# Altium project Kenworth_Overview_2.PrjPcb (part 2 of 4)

## Sheet T-Type_System.SchDoc: <Document>
size Letter; Engineer: <Engineer>; Organization: UPEL; Address1: USU Power Electronics Lab; Address2: USTAR Building 620, RM 118; Address3: 1600 N 620 E; Address4: North Logan, UT 84341; DocumentNumber: 8; Revision: v1; SheetNumber: 8; SheetTotal: 16
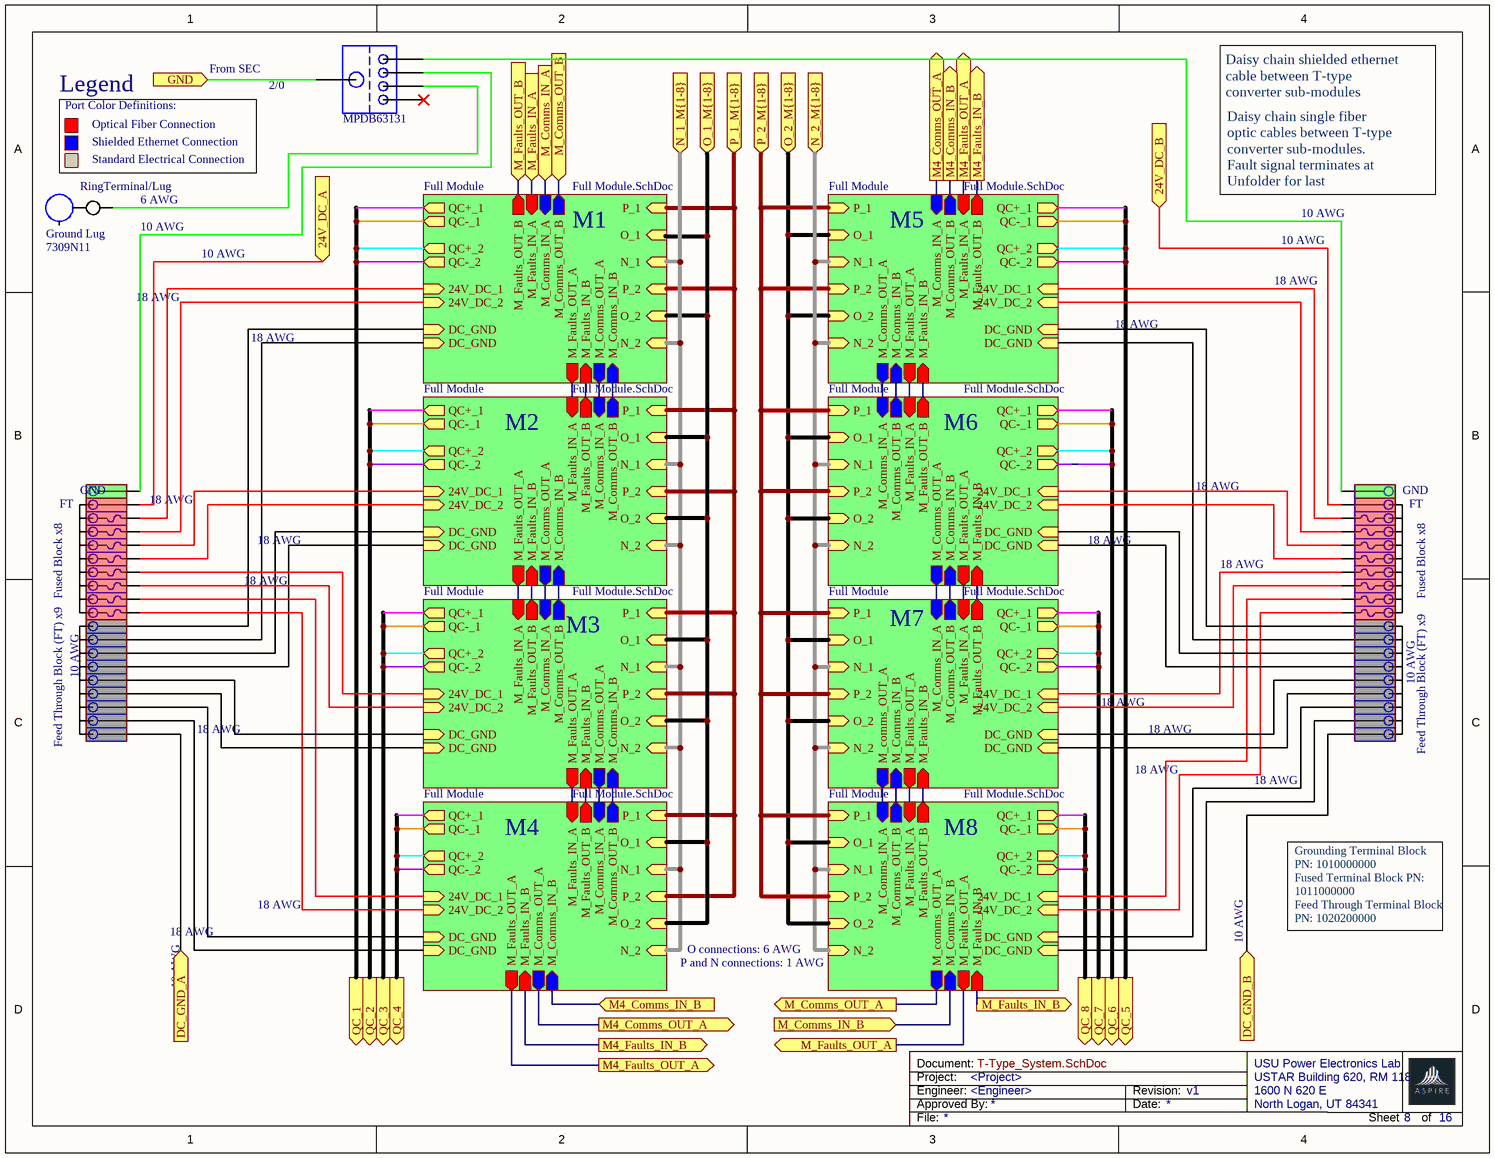
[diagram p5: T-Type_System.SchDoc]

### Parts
(Parts that share a designator on the sheet are numbered #1, #2 ... from top to bottom, then left to right.)
7309N11#1  Ground Lug
*#1  RingTerminal/Lug
J?#1  MPDB63131
J?#2  8_pos_terminal  (value not drawn)
J?#3  8_pos_terminal  (value not drawn)

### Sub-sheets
Full Module = Full Module.SchDoc (file not in this document): M_Faults_IN_B (in), M_Comms_OUT_A (out), M_Faults_IN_A (in), M_Comms_IN_A (in), P_1 (in), O_1 (in), N_1 (in), QC+_1 (out), QC-_1 (out), P_2 (in), O_2 (in), N_2 (in), QC+_2 (out), QC-_2 (out), DC_GND (in), 24V_DC_2 (in), 24V_DC_1 (in), DC_GND (in), M_Comms_OUT_B (out), M_Comms_IN_B (in), M_Faults_OUT_A (out), M_Faults_OUT_B (out)
Full Module = Full Module.SchDoc (file not in this document): M_Faults_IN_B (in), M_Comms_OUT_A (out), M_Faults_OUT_B (out), M_Comms_IN_A (in), P_1 (in), O_1 (in), N_1 (in), QC+_1 (out), QC-_1 (out), P_2 (in), O_2 (in), N_2 (in), QC+_2 (out), QC-_2 (out), DC_GND (in), DC_GND (in), 24V_DC_1 (in), 24V_DC_2 (in), M_Comms_OUT_B (out), M_Comms_IN_B (in), M_Faults_IN_A (in), M_Faults_OUT_A (out)
Full Module = Full Module.SchDoc (file not in this document): M_Faults_IN_B (in), M_comms_OUT_A (out), M_Faults_OUT_B (out), M_Comms_IN_A (in), P_1 (in), O_1 (in), N_1 (in), QC+_1 (out), QC-_1 (out), P_2 (in), O_2 (in), N_2 (in), QC+_2 (out), QC-_2 (out), DC_GND (in), DC_GND (in), 24V_DC_2 (in), 24V_DC_1 (in), M_Comms_OUT_B (out), M_Comms_IN_B (in), M_Faults_OUT_A (out), M_Faults_IN_A (in)
Full Module = Full Module.SchDoc (file not in this document): M_Faults_OUT_A (out), M_comms_OUT_A (out), M_Faults_OUT_B (out), M_Comms_IN_A (in), P_1 (in), O_1 (in), N_1 (in), QC+_1 (out), QC-_1 (out), P_2 (in), O_2 (in), N_2 (in), QC+_2 (out), QC-_2 (out), DC_GND (in), DC_GND (in), 24V_DC_2 (in), 24V_DC_1 (in), M_Comms_OUT_B (out), M_Comms_IN_B (in), M_Faults_IN_A (in), M_Faults_IN_B (in)
Full Module = Full Module.SchDoc (file not in this document): M_Faults_OUT_A (out), M_Comms_OUT_A (out), M_Faults_IN_A (in), M_Comms_IN_A (in), P_1 (in), O_1 (in), N_1 (in), QC+_1 (out), QC-_1 (out), P_2 (in), O_2 (in), N_2 (in), QC+_2 (out), QC-_2 (out), DC_GND (in), 24V_DC_2 (in), 24V_DC_1 (in), DC_GND (in), M_Comms_OUT_B (out), M_Comms_IN_B (in), M_Faults_OUT_B (out), M_Faults_IN_B (in)
Full Module = Full Module.SchDoc (file not in this document): M_Faults_OUT_A (out), M_Comms_OUT_A (out), M_Faults_IN_A (in), M_Comms_IN_A (in), P_1 (in), O_1 (in), N_1 (in), QC+_1 (out), QC-_1 (out), P_2 (in), O_2 (in), N_2 (in), QC+_2 (out), QC-_2 (out), DC_GND (in), DC_GND (in), 24V_DC_1 (in), 24V_DC_2 (in), M_Comms_OUT_B (out), M_Comms_IN_B (in), M_Faults_OUT_B (out), M_Faults_IN_B (in)
Full Module = Full Module.SchDoc (file not in this document): M_Faults_OUT_A (out), M_Comms_OUT_A (out), M_Faults_IN_A (in), M_Comms_IN_A (in), P_1 (in), O_1 (in), N_1 (in), QC+_1 (out), QC-_1 (out), P_2 (in), O_2 (in), N_2 (in), QC+_2 (out), QC-_2 (out), DC_GND (in), DC_GND (in), 24V_DC_2 (in), 24V_DC_1 (in), M_Comms_OUT_B (out), M_Comms_IN_B (in), M_Faults_OUT_B (out), M_Faults_IN_B (in)
Full Module = Full Module.SchDoc (file not in this document): M_Faults_OUT_A (out), M_Comms_OUT_A (out), M_Faults_IN_A (in), M_Comms_IN_A (in), P_1 (in), O_1 (in), N_1 (in), QC+_1 (out), QC-_1 (out), P_2 (in), O_2 (in), N_2 (in), QC+_2 (out), QC-_2 (out), DC_GND (in), DC_GND (in), 24V_DC_2 (in), 24V_DC_1 (in), M_Comms_OUT_B (out), M_Comms_IN_B (in), M_Faults_IN_B (in), M_Faults_OUT_B (out)

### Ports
24V_DC_A (in), 24V_DC_B (in), DC_GND_A (in), DC_GND_B (in), GND (in), M4_Comms_IN_B (in), M4_Comms_IN_B (out), M4_Comms_OUT_A (out), M4_Faults_IN_B (out), M4_Faults_OUT_A (out), M_Comms_IN_A (in), M_Comms_IN_B (in), M_Comms_OUT_A (out), M_Comms_OUT_B (in), M_Faults_IN_A (in), M_Faults_IN_B (out), M_Faults_OUT_A (out), M_Faults_OUT_B (in), N_1_M{1-8} (in), N_2_M{1-8} (in), O_1_M{1-8} (in), O_2_M{1-8} (in), P_1_M{1-8} (in), P_2_M{1-8} (in), QC_1 (out), QC_2 (out), QC_3 (out), QC_4 (out), QC_5 (out), QC_6 (out), QC_7 (out), QC_8 (out)

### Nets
24V_DC_A: J?#2.3 ; port 24V_DC_A
24V_DC_B: J?#3.3 ; port 24V_DC_B
DC_GND_A: J?#2.1 ; port DC_GND_A
DC_GND_B: J?#3.1 ; port DC_GND_B
GND: J?#1.0 ; port GND
M4_Comms_IN_B: port M4_Comms_IN_B, sheet Full Module/M_Comms_OUT_B, sheet Full Module/M_Comms_IN_B
M4_Comms_OUT_A: port M4_Comms_OUT_A, sheet Full Module/M_Comms_IN_A, sheet Full Module/M_Comms_OUT_A
M4_Faults_IN_B: port M4_Faults_IN_B, sheet Full Module/M_Faults_OUT_B, sheet Full Module/M_Faults_IN_B
M4_Faults_OUT_A: port M4_Faults_OUT_A, sheet Full Module/M_Faults_IN_A, sheet Full Module/M_Faults_OUT_A
M_Comms_IN_A: port M_Comms_IN_A, sheet Full Module/M_Comms_IN_A
M_Comms_IN_B: port M_Comms_IN_B, sheet Full Module/M_Comms_IN_B
M_Comms_OUT_A: port M_Comms_OUT_A, sheet Full Module/M_comms_OUT_A
M_Comms_OUT_B: port M_Comms_OUT_B, sheet Full Module/M_Comms_OUT_B
M_Faults_IN_A: port M_Faults_IN_A, sheet Full Module/M_Faults_IN_A
M_Faults_IN_B: port M_Faults_IN_B, sheet Full Module/M_Faults_IN_B
M_Faults_OUT_A: port M_Faults_OUT_A, sheet Full Module/M_Faults_OUT_A
M_Faults_OUT_B: port M_Faults_OUT_B, sheet Full Module/M_Faults_OUT_B
N_1_M{1-8}: port N_1_M{1-8}, sheet Full Module/N_1, sheet Full Module/N_2, sheet Full Module/N_1, sheet Full Module/N_2, sheet Full Module/N_1, sheet Full Module/N_2, sheet Full Module/N_1, sheet Full Module/N_2
N_2_M{1-8}: port N_2_M{1-8}, sheet Full Module/N_1, sheet Full Module/N_2, sheet Full Module/N_1, sheet Full Module/N_2, sheet Full Module/N_1, sheet Full Module/N_2, sheet Full Module/N_1, sheet Full Module/N_2
O_1_M{1-8}: port O_1_M{1-8}, sheet Full Module/O_2, sheet Full Module/O_1, sheet Full Module/O_2, sheet Full Module/O_1, sheet Full Module/O_2, sheet Full Module/O_1, sheet Full Module/O_2
O_2_M{1-8}: port O_2_M{1-8}, sheet Full Module/O_1, sheet Full Module/O_2, sheet Full Module/O_1, sheet Full Module/O_2, sheet Full Module/O_1, sheet Full Module/O_2, sheet Full Module/O_1, sheet Full Module/O_2
P_1_M{1-8}: port P_1_M{1-8}, sheet Full Module/P_1, sheet Full Module/P_2, sheet Full Module/P_1, sheet Full Module/P_2, sheet Full Module/P_1, sheet Full Module/P_2, sheet Full Module/P_1, sheet Full Module/P_2
P_2_M{1-8}: port P_2_M{1-8}, sheet Full Module/P_1, sheet Full Module/P_2, sheet Full Module/P_1, sheet Full Module/P_2, sheet Full Module/P_1, sheet Full Module/P_2, sheet Full Module/P_1, sheet Full Module/P_2
QC_1: port QC_1, sheet Full Module/QC+_1, sheet Full Module/QC-_1, sheet Full Module/QC+_2, sheet Full Module/QC-_2
QC_2: port QC_2, sheet Full Module/QC+_1, sheet Full Module/QC-_1, sheet Full Module/QC+_2, sheet Full Module/QC-_2
QC_3: port QC_3, sheet Full Module/QC+_1, sheet Full Module/QC-_1, sheet Full Module/QC+_2, sheet Full Module/QC-_2
QC_4: port QC_4, sheet Full Module/QC+_1, sheet Full Module/QC-_1, sheet Full Module/QC+_2, sheet Full Module/QC-_2
QC_5: port QC_5, sheet Full Module/QC+_1, sheet Full Module/QC-_1, sheet Full Module/QC+_2, sheet Full Module/QC-_2
QC_6: port QC_6, sheet Full Module/QC+_1, sheet Full Module/QC-_1, sheet Full Module/QC+_2, sheet Full Module/QC-_2
QC_7: port QC_7, sheet Full Module/QC+_1, sheet Full Module/QC-_1, sheet Full Module/QC+_2, sheet Full Module/QC-_2
QC_8: port QC_8, sheet Full Module/QC+_1, sheet Full Module/QC-_1, sheet Full Module/QC+_2, sheet Full Module/QC-_2
Net7309N11#1_5: 7309N11#1.5 *#1.2_13
Net*#1_2_12: *#1.2_12 J?#1.2
NetJ?#1_4: J?#1.4 J?#2.1
NetJ?#1_5: J?#1.5 J?#3.1
NetJ?#2_1: J?#2.1 ; sheet Full Module/DC_GND
NetJ?#2_1: J?#2.1 ; sheet Full Module/DC_GND  [a separate net that carries the same name]
NetJ?#2_1: J?#2.1 ; sheet Full Module/DC_GND  [a separate net that carries the same name]
NetJ?#2_1: J?#2.1 ; sheet Full Module/DC_GND  [a separate net that carries the same name]
NetJ?#2_1: J?#2.1 ; sheet Full Module/DC_GND  [a separate net that carries the same name]
NetJ?#2_1: J?#2.1 ; sheet Full Module/DC_GND  [a separate net that carries the same name]
NetJ?#2_1: J?#2.1 ; sheet Full Module/DC_GND  [a separate net that carries the same name]
NetJ?#2_1: J?#2.1 ; sheet Full Module/DC_GND  [a separate net that carries the same name]
NetJ?#2_3: J?#2.3 ; sheet Full Module/24V_DC_1
NetJ?#2_3: J?#2.3 ; sheet Full Module/24V_DC_2  [a separate net that carries the same name]
NetJ?#2_3: J?#2.3 ; sheet Full Module/24V_DC_2  [a separate net that carries the same name]
NetJ?#2_3: J?#2.3 ; sheet Full Module/24V_DC_1  [a separate net that carries the same name]
NetJ?#2_3: J?#2.3 ; sheet Full Module/24V_DC_2  [a separate net that carries the same name]
NetJ?#2_3: J?#2.3 ; sheet Full Module/24V_DC_1  [a separate net that carries the same name]
NetJ?#2_3: J?#2.3 ; sheet Full Module/24V_DC_2  [a separate net that carries the same name]
NetJ?#2_3: J?#2.3 ; sheet Full Module/24V_DC_1  [a separate net that carries the same name]
NetJ?#3_1: J?#3.1 ; sheet Full Module/DC_GND
NetJ?#3_1: J?#3.1 ; sheet Full Module/DC_GND  [a separate net that carries the same name]
NetJ?#3_1: J?#3.1 ; sheet Full Module/DC_GND  [a separate net that carries the same name]
NetJ?#3_1: J?#3.1 ; sheet Full Module/DC_GND  [a separate net that carries the same name]
NetJ?#3_1: J?#3.1 ; sheet Full Module/DC_GND  [a separate net that carries the same name]
NetJ?#3_1: J?#3.1 ; sheet Full Module/DC_GND  [a separate net that carries the same name]
NetJ?#3_1: J?#3.1 ; sheet Full Module/DC_GND  [a separate net that carries the same name]
NetJ?#3_1: J?#3.1 ; sheet Full Module/DC_GND  [a separate net that carries the same name]
NetJ?#3_3: J?#3.3 ; sheet Full Module/24V_DC_1
NetJ?#3_3: J?#3.3 ; sheet Full Module/24V_DC_2  [a separate net that carries the same name]
NetJ?#3_3: J?#3.3 ; sheet Full Module/24V_DC_2  [a separate net that carries the same name]
NetJ?#3_3: J?#3.3 ; sheet Full Module/24V_DC_1  [a separate net that carries the same name]
NetJ?#3_3: J?#3.3 ; sheet Full Module/24V_DC_2  [a separate net that carries the same name]
NetJ?#3_3: J?#3.3 ; sheet Full Module/24V_DC_1  [a separate net that carries the same name]
NetJ?#3_3: J?#3.3 ; sheet Full Module/24V_DC_2  [a separate net that carries the same name]
NetJ?#3_3: J?#3.3 ; sheet Full Module/24V_DC_1  [a separate net that carries the same name]
(unnamed): sheet Full Module/M_Faults_IN_B, sheet Full Module/M_Faults_OUT_B
(unnamed): sheet Full Module/M_Comms_OUT_A, sheet Full Module/M_Comms_IN_A  [a separate net that carries the same name]
(unnamed): sheet Full Module/M_Comms_IN_B, sheet Full Module/M_Comms_OUT_B  [a separate net that carries the same name]
(unnamed): sheet Full Module/M_Faults_OUT_A, sheet Full Module/M_Faults_IN_A  [a separate net that carries the same name]
(unnamed): sheet Full Module/M_Faults_IN_B, sheet Full Module/M_Faults_OUT_B  [a separate net that carries the same name]
(unnamed): sheet Full Module/M_Comms_OUT_A, sheet Full Module/M_Comms_IN_A  [a separate net that carries the same name]
(unnamed): sheet Full Module/M_Comms_IN_B, sheet Full Module/M_Comms_OUT_B  [a separate net that carries the same name]
(unnamed): sheet Full Module/M_Faults_OUT_A, sheet Full Module/M_Faults_IN_A  [a separate net that carries the same name]
(unnamed): sheet Full Module/M_Faults_IN_B, sheet Full Module/M_Faults_OUT_B  [a separate net that carries the same name]
(unnamed): sheet Full Module/M_comms_OUT_A, sheet Full Module/M_Comms_IN_A  [a separate net that carries the same name]
(unnamed): sheet Full Module/M_Comms_IN_B, sheet Full Module/M_Comms_OUT_B  [a separate net that carries the same name]
(unnamed): sheet Full Module/M_Faults_OUT_A, sheet Full Module/M_Faults_IN_A  [a separate net that carries the same name]
(unnamed): sheet Full Module/M_Faults_OUT_A, sheet Full Module/M_Faults_IN_A  [a separate net that carries the same name]
(unnamed): sheet Full Module/M_Comms_OUT_A, sheet Full Module/M_Comms_IN_A  [a separate net that carries the same name]
(unnamed): sheet Full Module/M_Comms_IN_B, sheet Full Module/M_Comms_OUT_B  [a separate net that carries the same name]
(unnamed): sheet Full Module/M_Faults_IN_B, sheet Full Module/M_Faults_OUT_B  [a separate net that carries the same name]
(unnamed): sheet Full Module/M_Faults_OUT_A, sheet Full Module/M_Faults_IN_A  [a separate net that carries the same name]
(unnamed): sheet Full Module/M_Comms_OUT_A, sheet Full Module/M_Comms_IN_A  [a separate net that carries the same name]
(unnamed): sheet Full Module/M_Comms_IN_B, sheet Full Module/M_Comms_OUT_B  [a separate net that carries the same name]
(unnamed): sheet Full Module/M_Faults_IN_B, sheet Full Module/M_Faults_OUT_B  [a separate net that carries the same name]
(unnamed): sheet Full Module/M_Faults_OUT_A, sheet Full Module/M_Faults_IN_A  [a separate net that carries the same name]
(unnamed): sheet Full Module/M_Comms_OUT_A, sheet Full Module/M_Comms_IN_A  [a separate net that carries the same name]
(unnamed): sheet Full Module/M_Comms_IN_B, sheet Full Module/M_Comms_OUT_B  [a separate net that carries the same name]
(unnamed): sheet Full Module/M_Faults_IN_B, sheet Full Module/M_Faults_OUT_B  [a separate net that carries the same name]

Not connected (* = marked no-connect by the designer): J?#1 1*

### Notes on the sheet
- Legend
- From SEC
- 2/0
- Port Color Definitions:
- Optical Fiber Connection
- Shielded Ethernet Connection
- Standard Electrical Connection
- Daisy chain shielded ethernet
  cable between T-type
  converter sub-modules
- 10 AWG
- 6 AWG
- M1
- M5
- Daisy chain single fiber
  optic cables between T-type
  converter sub-modules.
  Fault signal terminates at
  Unfolder for last
- 18 AWG
- M2
- M6
- (near J?#2) FT
- (near J?#2) GND
- (near J?#3) GND
- (near J?#3) FT
- (near J?#2) Fused Block x8
- (near J?#2) 10 AWG
- M3
- M7
- (near J?#3) 10 AWG
- (near J?#3) Fused Block x8
- (near J?#2) Feed Through Block (FT) x9
- (near J?#3) Feed Through Block (FT) x9
- M4
- M8
- Grounding Terminal Block PN: 1010000000
- Fused Terminal Block PN: 1011000000
- P and N connections: 1 AWG
- O connections: 6 AWG
- Feed Through Terminal Block PN: 1020200000

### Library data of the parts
7309N11#1 = 7309N11
J?#1 = 4_to_1
J?#2 J?#3 = Full_Terminal_Block

## Sheet Coolant_System.SchDoc: <Document>
size Letter; Engineer: <Engineer>; Organization: UPEL; Address1: USU Power Electronics Lab; Address2: USTAR Building 620, RM 118; Address3: 1600 N 620 E; Address4: North Logan, UT 84341; DocumentNumber: 15; Revision: v1; SheetNumber: 15; SheetTotal: 16
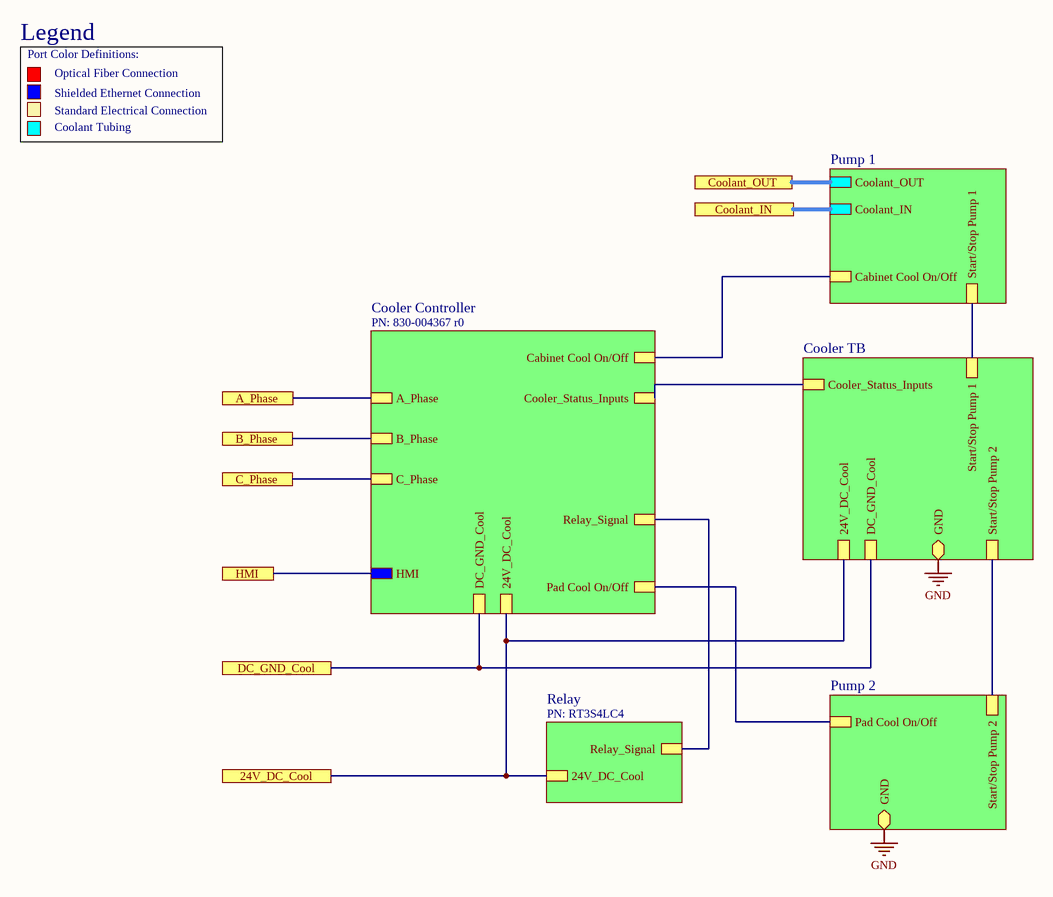
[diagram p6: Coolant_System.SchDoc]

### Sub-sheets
Designator = Cooler Controller (file not in this document): DC_GND_Cool, 24V_DC_Cool, HMI, A_Phase, B_Phase, C_Phase, Relay_Signal, Cooler_Status_Inputs, Pad Cool On/Off, Cabinet Cool On/Off
Designator = Pump 1 (file not in this document): Cabinet Cool On/Off, Coolant_OUT, Coolant_IN, Start/Stop Pump 1
Designator = Pump 2 (file not in this document): Pad Cool On/Off, Start/Stop Pump 2, GND (bidir)
Designator = Cooler TB (file not in this document): Cooler_Status_Inputs, 24V_DC_Cool, DC_GND_Cool, GND (bidir), Start/Stop Pump 1, Start/Stop Pump 2
Relay = Relay (file not in this document): 24V_DC_Cool, Relay_Signal

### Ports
24V_DC_Cool, A_Phase, B_Phase, C_Phase, Coolant_IN, Coolant_OUT, DC_GND_Cool, HMI

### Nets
GND: sheet Designator/GND, sheet Designator/GND
24V_DC_Cool: port 24V_DC_Cool, sheet Relay/24V_DC_Cool, sheet Designator/24V_DC_Cool, sheet Designator/24V_DC_Cool
A_Phase: port A_Phase, sheet Designator/A_Phase
B_Phase: port B_Phase, sheet Designator/B_Phase
C_Phase: port C_Phase, sheet Designator/C_Phase
Coolant_IN: port Coolant_IN, sheet Designator/Coolant_IN
Coolant_OUT: port Coolant_OUT, sheet Designator/Coolant_OUT
DC_GND_Cool: port DC_GND_Cool, sheet Designator/DC_GND_Cool, sheet Designator/DC_GND_Cool
HMI: port HMI, sheet Designator/HMI
(unnamed): sheet Relay/Relay_Signal, sheet Designator/Relay_Signal
(unnamed): sheet Designator/Cooler_Status_Inputs, sheet Designator/Cooler_Status_Inputs  [a separate net that carries the same name]
(unnamed): sheet Designator/Pad Cool On/Off, sheet Designator/Pad Cool On/Off  [a separate net that carries the same name]
(unnamed): sheet Designator/Cabinet Cool On/Off, sheet Designator/Cabinet Cool On/Off  [a separate net that carries the same name]
(unnamed): sheet Designator/Start/Stop Pump 1, sheet Designator/Start/Stop Pump 1  [a separate net that carries the same name]
(unnamed): sheet Designator/Start/Stop Pump 2, sheet Designator/Start/Stop Pump 2  [a separate net that carries the same name]

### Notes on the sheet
- Legend
- Port Color Definitions:
- Optical Fiber Connection
- Shielded Ethernet Connection
- Standard Electrical Connection
- Coolant Tubing
- PN: 830-004367 r0
- PN: RT3S4LC4

## Sheet Current_and_Water_Sensing_System.SchDoc
size A
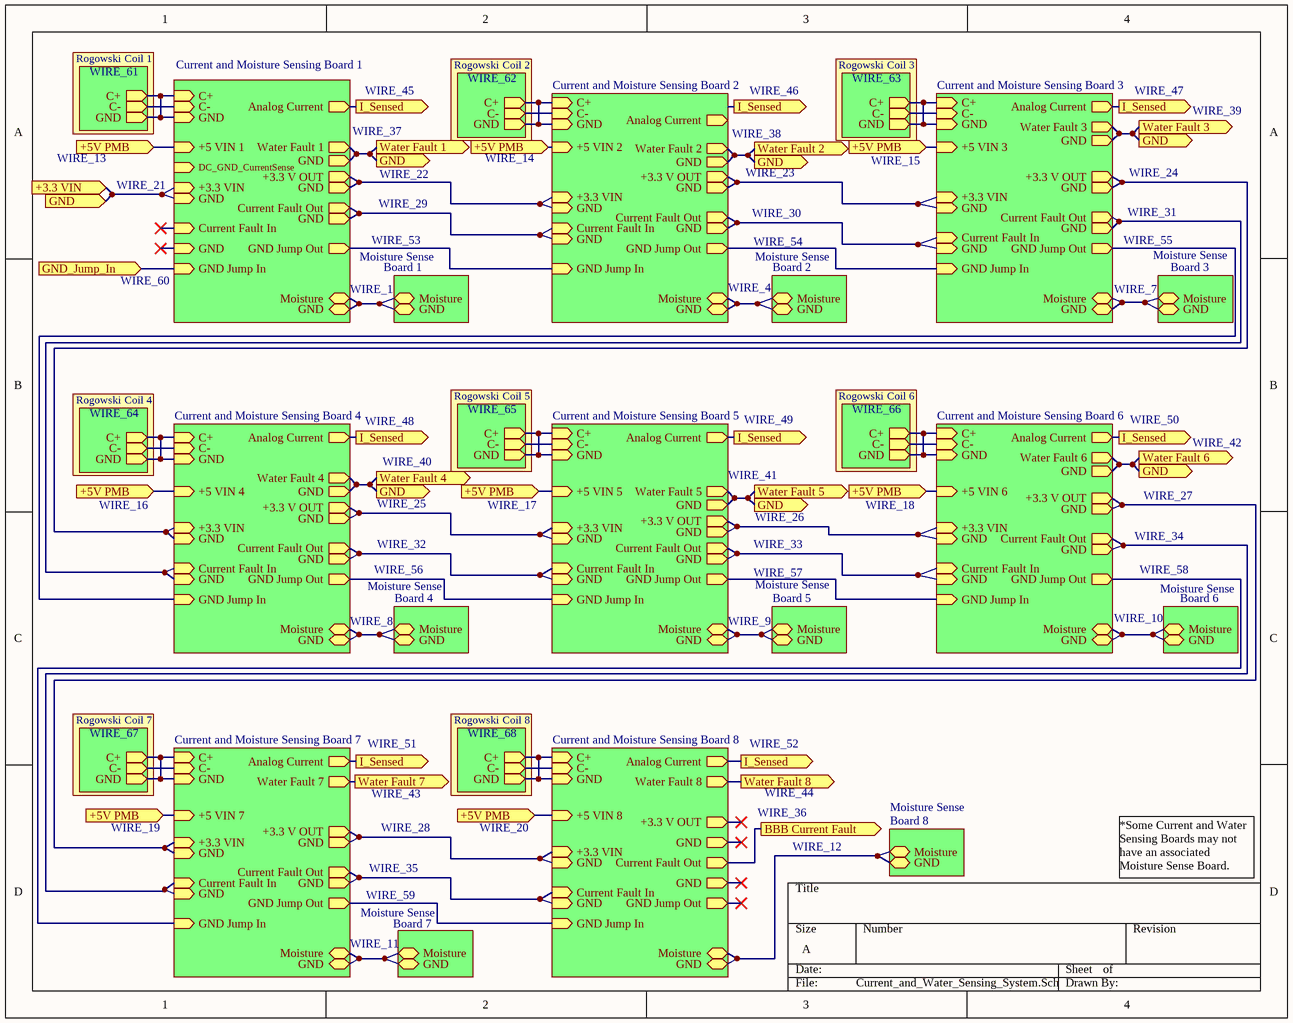
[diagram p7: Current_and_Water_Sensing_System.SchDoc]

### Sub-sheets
Board 1 = File Name (file not in this document): GND (bidir), Moisture (bidir)
Board 2 = File Name (file not in this document): GND (bidir), Moisture (bidir)
Board 3 = File Name (file not in this document): GND (bidir), Moisture (bidir)
Board 4 = File Name (file not in this document): GND (bidir), Moisture (bidir)
Board 5 = File Name (file not in this document): GND (bidir), Moisture (bidir)
Board 6 = File Name (file not in this document): GND (bidir), Moisture (bidir)
Board 7 = File Name (file not in this document): GND (bidir), Moisture (bidir)
Board 8 = File Name (file not in this document): GND (bidir), Moisture (bidir)
Coil 1 = File Name (file not in this document): GND (out), C- (out), C+ (out)
Coil 2 = File Name (file not in this document): GND (out), C- (out), C+ (out)
Coil 3 = File Name (file not in this document): GND (out), C- (out), C+ (out)
Coil 4 = File Name (file not in this document): GND (out), C- (out), C+ (out)
Coil 5 = File Name (file not in this document): GND (out), C- (out), C+ (out)
Coil 6 = File Name (file not in this document): GND (out), C- (out), C+ (out)
Coil 7 = File Name (file not in this document): GND (out), C- (out), C+ (out)
Coil 8 = File Name (file not in this document): GND (out), C- (out), C+ (out)
Current and Moisture Sensing Board 1 = File Name (file not in this document): C- (in), GND (in), Analog Current (out), Water Fault 1 (out), GND (bidir), +3.3 V OUT (out), GND Jump Out (out), +5 VIN 1 (in), +3.3 VIN (in), Current Fault Out (out), Moisture (bidir), Current Fault In (in), GND (in), GND (in), GND (out), GND (out), GND Jump In (in), DC_GND_CurrentSense (in), GND (out), C+ (in)
Current and Moisture Sensing Board 2 = File Name (file not in this document): Analog Current (out), Water Fault 2 (out), GND (bidir), +3.3 V OUT (out), GND Jump Out (out), +5 VIN 2 (in), +3.3 VIN (in), Current Fault Out (out), Moisture (bidir), Current Fault In (in), GND (in), GND (in), GND (out), GND (out), GND Jump In (in), GND (out), C- (in), GND (in), C+ (in)
Current and Moisture Sensing Board 3 = File Name (file not in this document): Analog Current (out), Water Fault 3 (out), GND (bidir), +3.3 V OUT (out), GND Jump Out (out), +5 VIN 3 (in), +3.3 VIN (in), Current Fault Out (out), Moisture (bidir), Current Fault In (in), GND (in), GND (in), GND (out), GND (out), GND Jump In (in), GND (out), C- (in), GND (in), C+ (in)
Current and Moisture Sensing Board 4 = File Name (file not in this document): Analog Current (out), Water Fault 4 (out), GND (bidir), +3.3 V OUT (out), GND Jump Out (out), +5 VIN 4 (in), +3.3 VIN (in), Current Fault Out (out), Moisture (bidir), Current Fault In (in), GND (in), GND (in), GND (out), GND (out), GND Jump In (in), GND (out), C- (in), GND (in), C+ (in)
Current and Moisture Sensing Board 5 = File Name (file not in this document): Analog Current (out), Water Fault 5 (out), GND (bidir), +3.3 V OUT (out), GND Jump Out (out), +5 VIN 5 (in), +3.3 VIN (in), Current Fault Out (out), Moisture (bidir), Current Fault In (in), GND (in), GND (in), GND (out), GND (out), GND Jump In (in), GND (out), C- (in), GND (in), C+ (in)
Current and Moisture Sensing Board 6 = File Name (file not in this document): Analog Current (out), Water Fault 6 (out), GND (bidir), +3.3 V OUT (out), GND Jump Out (out), +5 VIN 6 (in), +3.3 VIN (in), Current Fault Out (out), Moisture (bidir), Current Fault In (in), GND (in), GND (in), GND (out), GND (out), GND Jump In (in), GND (out), C- (in), GND (in), C+ (in)
Current and Moisture Sensing Board 7 = File Name (file not in this document): Analog Current (out), Water Fault 7 (out), +3.3 V OUT (out), GND Jump Out (out), +5 VIN 7 (in), +3.3 VIN (in), Current Fault Out (out), Current Fault In (in), GND (in), GND (in), GND (out), GND (out), GND Jump In (in), Moisture (bidir), GND (bidir), C- (in), GND (in), C+ (in)
Current and Moisture Sensing Board 8 = File Name (file not in this document): Analog Current (out), Water Fault 8 (out), +3.3 V OUT (out), GND Jump Out (out), +5 VIN 8 (in), +3.3 VIN (in), Current Fault Out (out), Current Fault In (in), GND (in), GND (in), GND (out), GND (out), GND Jump In (in), Moisture (bidir), GND (bidir), C- (in), GND (in), C+ (in)

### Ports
+3.3 VIN (in), +5V PMB (in), BBB Current Fault (out), GND (in), GND (out), GND_Jump_In (in), I_Sensed (out), Water Fault 1 (out), Water Fault 2 (out), Water Fault 3 (out), Water Fault 4 (out), Water Fault 5 (out), Water Fault 6 (out), Water Fault 7 (out), Water Fault 8 (out)

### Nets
+3.3 VIN: port Water Fault 1, port Water Fault 4, port Water Fault 2, port Water Fault 5, port Water Fault 3, port Water Fault 6, port +3.3 VIN, port GND, sheet Current and Moisture Sensing Board 2/Water Fault 2, sheet Current and Moisture Sensing Board 2/GND, sheet Current and Moisture Sensing Board 1/Water Fault 1, sheet Current and Moisture Sensing Board 1/+3.3 VIN, sheet Current and Moisture Sensing Board 1/GND, sheet Current and Moisture Sensing Board 1/GND, sheet Current and Moisture Sensing Board 4/Water Fault 4, sheet Current and Moisture Sensing Board 4/GND, sheet Current and Moisture Sensing Board 5/Water Fault 5, sheet Current and Moisture Sensing Board 5/GND, sheet Current and Moisture Sensing Board 6/Water Fault 6, sheet Current and Moisture Sensing Board 6/GND, sheet Current and Moisture Sensing Board 3/Water Fault 3, sheet Current and Moisture Sensing Board 3/GND
+5V PMB: port +5V PMB, sheet Current and Moisture Sensing Board 2/+5 VIN 2, sheet Current and Moisture Sensing Board 1/+5 VIN 1, sheet Current and Moisture Sensing Board 4/+5 VIN 4, sheet Current and Moisture Sensing Board 7/+5 VIN 7, sheet Current and Moisture Sensing Board 5/+5 VIN 5, sheet Current and Moisture Sensing Board 6/+5 VIN 6, sheet Current and Moisture Sensing Board 3/+5 VIN 3, sheet Current and Moisture Sensing Board 8/+5 VIN 8
BBB Current Fault: port BBB Current Fault, sheet Current and Moisture Sensing Board 8/Current Fault Out
GND_Jump_In: port GND_Jump_In, sheet Current and Moisture Sensing Board 1/GND Jump In
I_Sensed: port I_Sensed, sheet Current and Moisture Sensing Board 1/Analog Current, sheet Current and Moisture Sensing Board 4/Analog Current, sheet Current and Moisture Sensing Board 7/Analog Current, sheet Current and Moisture Sensing Board 5/Analog Current, sheet Current and Moisture Sensing Board 6/Analog Current, sheet Current and Moisture Sensing Board 3/Analog Current, sheet Current and Moisture Sensing Board 8/Analog Current
Water Fault 7: port Water Fault 7, sheet Current and Moisture Sensing Board 7/Water Fault 7
Water Fault 8: port Water Fault 8, sheet Current and Moisture Sensing Board 8/Water Fault 8
(unnamed): sheet Current and Moisture Sensing Board 2/GND, sheet Current and Moisture Sensing Board 2/Moisture, sheet Board 2/GND, sheet Board 2/Moisture
(unnamed): sheet Current and Moisture Sensing Board 2/+3.3 V OUT, sheet Current and Moisture Sensing Board 2/GND, sheet Current and Moisture Sensing Board 3/+3.3 VIN, sheet Current and Moisture Sensing Board 3/GND  [a separate net that carries the same name]
(unnamed): sheet Current and Moisture Sensing Board 2/GND Jump Out, sheet Current and Moisture Sensing Board 3/GND Jump In  [a separate net that carries the same name]
(unnamed): sheet Current and Moisture Sensing Board 2/+3.3 VIN, sheet Current and Moisture Sensing Board 2/GND, sheet Current and Moisture Sensing Board 1/+3.3 V OUT, sheet Current and Moisture Sensing Board 1/GND  [a separate net that carries the same name]
(unnamed): sheet Current and Moisture Sensing Board 2/Current Fault Out, sheet Current and Moisture Sensing Board 2/GND, sheet Current and Moisture Sensing Board 3/Current Fault In, sheet Current and Moisture Sensing Board 3/GND  [a separate net that carries the same name]
(unnamed): sheet Current and Moisture Sensing Board 2/Current Fault In, sheet Current and Moisture Sensing Board 2/GND, sheet Current and Moisture Sensing Board 1/Current Fault Out, sheet Current and Moisture Sensing Board 1/GND  [a separate net that carries the same name]
(unnamed): sheet Current and Moisture Sensing Board 2/GND Jump In, sheet Current and Moisture Sensing Board 1/GND Jump Out  [a separate net that carries the same name]
(unnamed): sheet Current and Moisture Sensing Board 2/C-, sheet Coil 2/C-  [a separate net that carries the same name]
(unnamed): sheet Current and Moisture Sensing Board 2/GND, sheet Current and Moisture Sensing Board 2/C+, sheet Coil 2/GND, sheet Coil 2/C+  [a separate net that carries the same name]
(unnamed): sheet Board 1/GND, sheet Board 1/Moisture, sheet Current and Moisture Sensing Board 1/GND, sheet Current and Moisture Sensing Board 1/Moisture  [a separate net that carries the same name]
(unnamed): sheet Current and Moisture Sensing Board 1/C-, sheet Coil 1/C-  [a separate net that carries the same name]
(unnamed): sheet Current and Moisture Sensing Board 1/GND, sheet Current and Moisture Sensing Board 1/C+, sheet Coil 1/GND, sheet Coil 1/C+  [a separate net that carries the same name]
(unnamed): sheet Current and Moisture Sensing Board 4/GND, sheet Current and Moisture Sensing Board 4/Moisture, sheet Board 4/GND, sheet Board 4/Moisture  [a separate net that carries the same name]
(unnamed): sheet Current and Moisture Sensing Board 4/+3.3 V OUT, sheet Current and Moisture Sensing Board 4/GND, sheet Current and Moisture Sensing Board 5/+3.3 VIN, sheet Current and Moisture Sensing Board 5/GND  [a separate net that carries the same name]
(unnamed): sheet Current and Moisture Sensing Board 4/GND Jump Out, sheet Current and Moisture Sensing Board 5/GND Jump In  [a separate net that carries the same name]
(unnamed): sheet Current and Moisture Sensing Board 4/+3.3 VIN, sheet Current and Moisture Sensing Board 4/GND, sheet Current and Moisture Sensing Board 3/+3.3 V OUT, sheet Current and Moisture Sensing Board 3/GND  [a separate net that carries the same name]
(unnamed): sheet Current and Moisture Sensing Board 4/Current Fault Out, sheet Current and Moisture Sensing Board 4/GND, sheet Current and Moisture Sensing Board 5/Current Fault In, sheet Current and Moisture Sensing Board 5/GND  [a separate net that carries the same name]
(unnamed): sheet Current and Moisture Sensing Board 4/Current Fault In, sheet Current and Moisture Sensing Board 4/GND, sheet Current and Moisture Sensing Board 3/Current Fault Out, sheet Current and Moisture Sensing Board 3/GND  [a separate net that carries the same name]
(unnamed): sheet Current and Moisture Sensing Board 4/GND Jump In, sheet Current and Moisture Sensing Board 3/GND Jump Out  [a separate net that carries the same name]
(unnamed): sheet Current and Moisture Sensing Board 4/C-, sheet Coil 4/C-  [a separate net that carries the same name]
(unnamed): sheet Current and Moisture Sensing Board 4/GND, sheet Current and Moisture Sensing Board 4/C+, sheet Coil 4/GND, sheet Coil 4/C+  [a separate net that carries the same name]
(unnamed): sheet Current and Moisture Sensing Board 7/+3.3 V OUT, sheet Current and Moisture Sensing Board 7/GND, sheet Current and Moisture Sensing Board 8/+3.3 VIN, sheet Current and Moisture Sensing Board 8/GND  [a separate net that carries the same name]
(unnamed): sheet Current and Moisture Sensing Board 7/GND Jump Out, sheet Current and Moisture Sensing Board 8/GND Jump In  [a separate net that carries the same name]
(unnamed): sheet Current and Moisture Sensing Board 7/+3.3 VIN, sheet Current and Moisture Sensing Board 7/GND, sheet Current and Moisture Sensing Board 6/+3.3 V OUT, sheet Current and Moisture Sensing Board 6/GND  [a separate net that carries the same name]
(unnamed): sheet Current and Moisture Sensing Board 7/Current Fault Out, sheet Current and Moisture Sensing Board 7/GND, sheet Current and Moisture Sensing Board 8/Current Fault In, sheet Current and Moisture Sensing Board 8/GND  [a separate net that carries the same name]
(unnamed): sheet Current and Moisture Sensing Board 7/Current Fault In, sheet Current and Moisture Sensing Board 7/GND, sheet Current and Moisture Sensing Board 6/Current Fault Out, sheet Current and Moisture Sensing Board 6/GND  [a separate net that carries the same name]
(unnamed): sheet Current and Moisture Sensing Board 7/GND Jump In, sheet Current and Moisture Sensing Board 6/GND Jump Out  [a separate net that carries the same name]
(unnamed): sheet Current and Moisture Sensing Board 7/Moisture, sheet Current and Moisture Sensing Board 7/GND, sheet Board 7/GND, sheet Board 7/Moisture  [a separate net that carries the same name]
(unnamed): sheet Current and Moisture Sensing Board 7/C-, sheet Coil 7/C-  [a separate net that carries the same name]
(unnamed): sheet Current and Moisture Sensing Board 7/GND, sheet Current and Moisture Sensing Board 7/C+, sheet Coil 7/GND, sheet Coil 7/C+  [a separate net that carries the same name]
(unnamed): sheet Current and Moisture Sensing Board 5/GND, sheet Current and Moisture Sensing Board 5/Moisture, sheet Board 5/GND, sheet Board 5/Moisture  [a separate net that carries the same name]
(unnamed): sheet Current and Moisture Sensing Board 5/+3.3 V OUT, sheet Current and Moisture Sensing Board 5/GND, sheet Current and Moisture Sensing Board 6/+3.3 VIN, sheet Current and Moisture Sensing Board 6/GND  [a separate net that carries the same name]
(unnamed): sheet Current and Moisture Sensing Board 5/GND Jump Out, sheet Current and Moisture Sensing Board 6/GND Jump In  [a separate net that carries the same name]
(unnamed): sheet Current and Moisture Sensing Board 5/Current Fault Out, sheet Current and Moisture Sensing Board 5/GND, sheet Current and Moisture Sensing Board 6/Current Fault In, sheet Current and Moisture Sensing Board 6/GND  [a separate net that carries the same name]
(unnamed): sheet Current and Moisture Sensing Board 5/C-, sheet Coil 5/C-  [a separate net that carries the same name]
(unnamed): sheet Current and Moisture Sensing Board 5/GND, sheet Current and Moisture Sensing Board 5/C+, sheet Coil 5/GND, sheet Coil 5/C+  [a separate net that carries the same name]
(unnamed): sheet Current and Moisture Sensing Board 6/GND, sheet Current and Moisture Sensing Board 6/Moisture, sheet Board 6/GND, sheet Board 6/Moisture  [a separate net that carries the same name]
(unnamed): sheet Current and Moisture Sensing Board 6/C-, sheet Coil 6/C-  [a separate net that carries the same name]
(unnamed): sheet Current and Moisture Sensing Board 6/GND, sheet Current and Moisture Sensing Board 6/C+, sheet Coil 6/GND, sheet Coil 6/C+  [a separate net that carries the same name]
(unnamed): sheet Current and Moisture Sensing Board 3/GND, sheet Current and Moisture Sensing Board 3/Moisture, sheet Board 3/GND, sheet Board 3/Moisture  [a separate net that carries the same name]
(unnamed): sheet Current and Moisture Sensing Board 3/C-, sheet Coil 3/C-  [a separate net that carries the same name]
(unnamed): sheet Current and Moisture Sensing Board 3/GND, sheet Current and Moisture Sensing Board 3/C+, sheet Coil 3/GND, sheet Coil 3/C+  [a separate net that carries the same name]
(unnamed): sheet Current and Moisture Sensing Board 8/Moisture, sheet Current and Moisture Sensing Board 8/GND, sheet Board 8/GND, sheet Board 8/Moisture  [a separate net that carries the same name]
(unnamed): sheet Current and Moisture Sensing Board 8/C-, sheet Coil 8/C-  [a separate net that carries the same name]
(unnamed): sheet Current and Moisture Sensing Board 8/GND, sheet Current and Moisture Sensing Board 8/C+, sheet Coil 8/GND, sheet Coil 8/C+  [a separate net that carries the same name]

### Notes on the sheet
- Rogowski
- WIRE_61
- WIRE_45
- WIRE_62
- WIRE_46
- WIRE_63
- WIRE_47
- WIRE_13
- WIRE_37
- WIRE_14
- WIRE_38
- WIRE_15
- WIRE_39
- WIRE_21
- WIRE_29
- WIRE_22
- WIRE_23
- WIRE_30
- WIRE_31
- WIRE_24
- WIRE_60
- WIRE_1
- Moisture Sense
- WIRE_53
- WIRE_4
- WIRE_54
- WIRE_7
- WIRE_55
- WIRE_64
- WIRE_48
- WIRE_65
- WIRE_49
- WIRE_66
- WIRE_50
- WIRE_25
- WIRE_40
- WIRE_41
- WIRE_27
- WIRE_42
- WIRE_16
- WIRE_56
- WIRE_32
- WIRE_17
- WIRE_33
- WIRE_26
- WIRE_18
- WIRE_34
- WIRE_58
- WIRE_8
- WIRE_9
- WIRE_57
- WIRE_10
- WIRE_67
- WIRE_51
- WIRE_68
- WIRE_52
- WIRE_19
- WIRE_43
- WIRE_28
- WIRE_20
- WIRE_36
- WIRE_44
- WIRE_59
- WIRE_35
- WIRE_12
- *Some Current and Water Sensing Boards may not have an associated Moisture Sense Board.
- WIRE_11

## Sheet Top_Overview.SchDoc: <Document>
size Letter; Engineer: <Engineer>; Organization: UPEL; Address1: USU Power Electronics Lab; Address2: USTAR Building 620, RM 118; Address3: 1600 N 620 E; Address4: North Logan, UT 84341; DocumentNumber: 1; Revision: v1; SheetNumber: 1; SheetTotal: 16
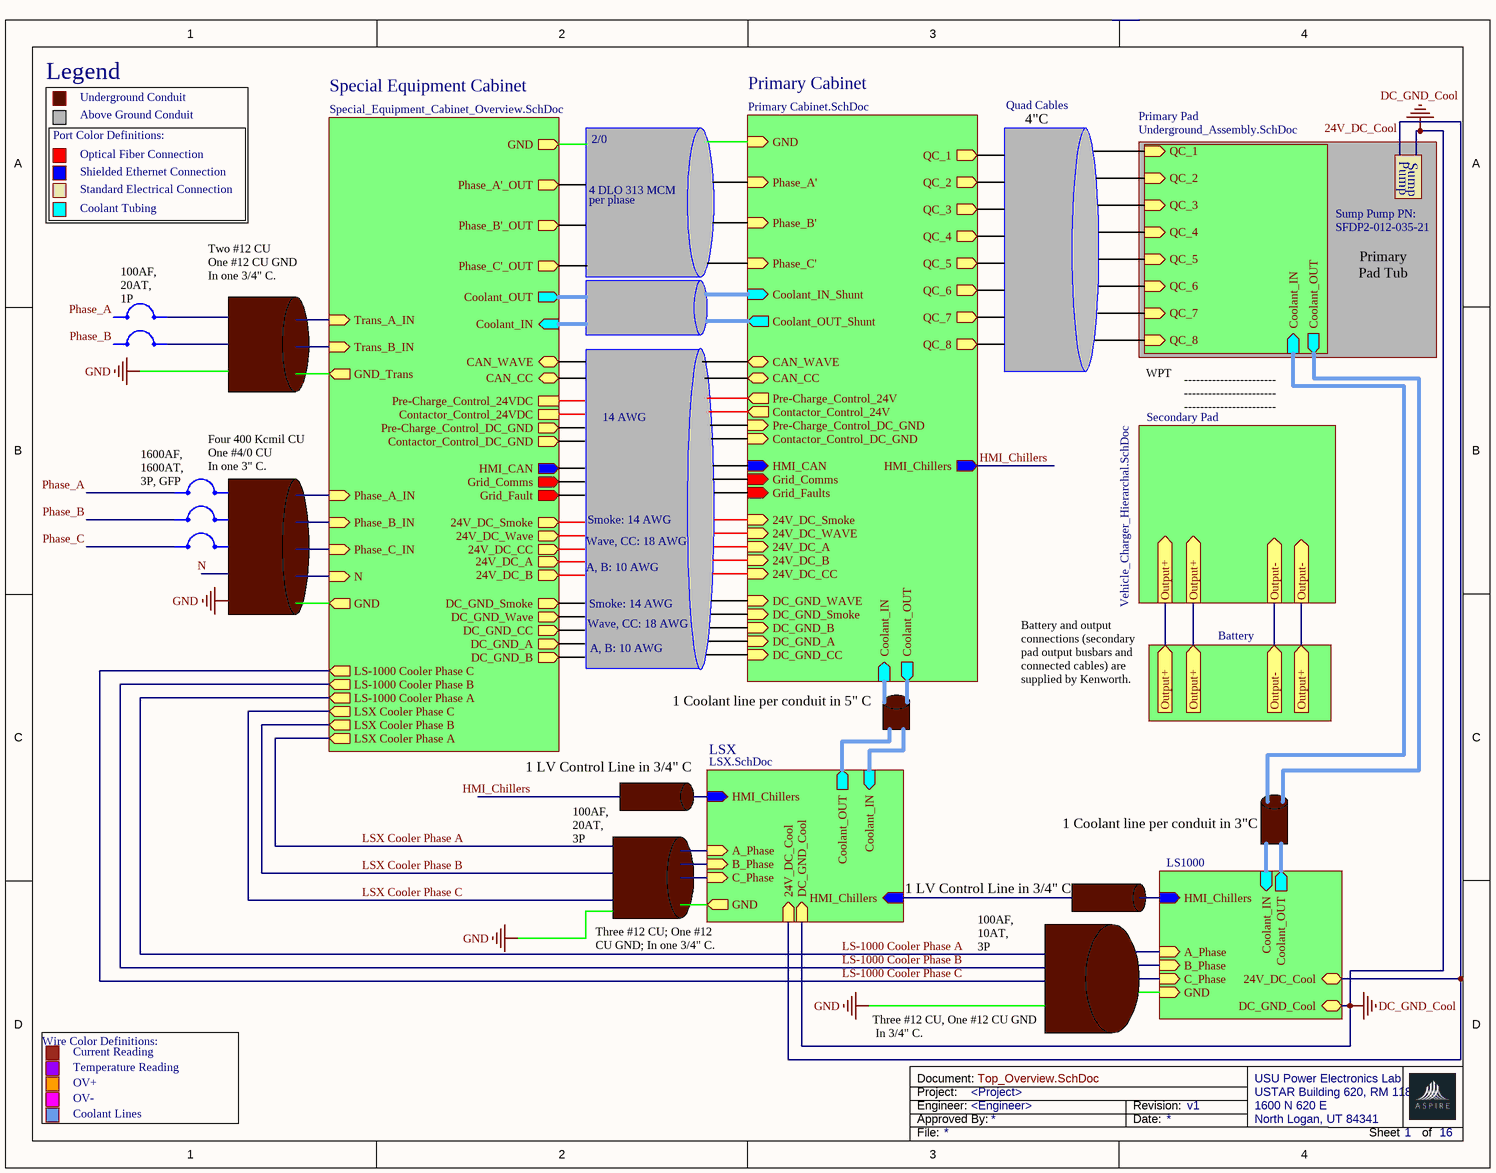
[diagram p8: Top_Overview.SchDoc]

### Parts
B1  Breaker  (value not drawn)
B2  Breaker  (value not drawn)
B3  Breaker  (value not drawn)
B6  Breaker  (value not drawn)
B7  Breaker  (value not drawn)

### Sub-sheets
Designator = File Name (file not in this document): no entries
LS1000 = File Name (file not in this document): A_Phase (in), B_Phase (in), C_Phase (in), GND (in), HMI_Chillers (in), 24V_DC_Cool (bidir), DC_GND_Cool (bidir), Coolant_OUT (out), Coolant_IN (in)
LSX = LSX.SchDoc (file not in this document): A_Phase (in), B_Phase (in), C_Phase (in), GND (out), HMI_Chillers (in), 24V_DC_Cool (in), Coolant_OUT (out), DC_GND_Cool (in), Coolant_IN (in), HMI_Chillers (in)
Primary Cabinet = Primary Cabinet.SchDoc (file not in this document): Phase_A' (in), Phase_B' (in), Phase_C' (in), HMI_CAN (in), Grid_Comms (in), Grid_Faults (in), Coolant_IN (in), Coolant_OUT (out), Coolant_IN_Shunt (in), Coolant_OUT_Shunt (out), QC_2 (out), QC_1 (out), QC_3 (out), QC_6 (out), QC_7 (out), QC_8 (out), QC_5 (out), QC_4 (out), GND (in), Pre-Charge_Control_24V (out), Contactor_Control_24V (out), Contactor_Control_DC_GND (in), Pre-Charge_Control_DC_GND (in), 24V_DC_WAVE (in), DC_GND_WAVE (in), 24V_DC_A (in), 24V_DC_B (in), DC_GND_A (in), DC_GND_B (in), 24V_DC_CC (in), DC_GND_CC (in), HMI_Chillers (out), 24V_DC_Smoke (in), DC_GND_Smoke (in), CAN_WAVE (bidir), CAN_CC (bidir)
Primary Pad = Underground_Assembly.SchDoc: Coolant_OUT (out), Coolant_IN (in), QC_1 (in), QC_2 (in), QC_3 (in), QC_4 (in), QC_5 (in), QC_6 (in), QC_7 (in), QC_8 (in)
Secondary Pad = Vehicle_Charger_Hierarchal.SchDoc: no entries
Special Equipment Cabinet = Special_Equipment_Cabinet_Overview.SchDoc: HMI_CAN (out), GND (out), N (in), Grid_Fault (out), Grid_Comms (out), GND_Trans (out), Coolant_IN (in), Coolant_OUT (out), Phase_A_IN (in), Trans_A_IN (in), Trans_B_IN (in), Phase_B_IN (in), Phase_C_IN (in), Phase_A'_OUT (out), Phase_B'_OUT (out), Phase_C'_OUT (out), GND (out), Contactor_Control_24VDC, Pre-Charge_Control_24VDC, Contactor_Control_DC_GND (out), Pre-Charge_Control_DC_GND (out), 24V_DC_CC (out), 24V_DC_Wave (out), 24V_DC_B (out), 24V_DC_A (out), DC_GND_B (out), DC_GND_A (out), DC_GND_Wave (out), DC_GND_CC (out), 24V_DC_Smoke (out), DC_GND_Smoke (out), LSX Cooler Phase A (out), LSX Cooler Phase B (out), LSX Cooler Phase C (out), LS-1000 Cooler Phase A (out), LS-1000 Cooler Phase B (out), LS-1000 Cooler Phase C (out), CAN_WAVE (bidir), CAN_CC (bidir)

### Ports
Output+ (in), Output+ (out), Output- (in), Output- (out)

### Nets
DC_GND_Cool: sheet LS1000/DC_GND_Cool, sheet LSX/DC_GND_Cool
CAN_CC: sheet Special Equipment Cabinet/CAN_WAVE, sheet Special Equipment Cabinet/CAN_CC
GND: sheet Special Equipment Cabinet/GND, sheet Special Equipment Cabinet/GND
Output+: port Output+, port Output-
Phase_A: B1.0 B6.0
Phase_B: B2.0 B7.0
Phase_C: B3.0
(unnamed): sheet LS1000/24V_DC_Cool, sheet LSX/24V_DC_Cool

Not connected (* = marked no-connect by the designer): B1 1; B2 1; B3 1; B6 1; B7 1

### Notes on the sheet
- Legend
- Underground Conduit
- Quad Cables
- Port Color Definitions:
- Optical Fiber Connection
- Shielded Ethernet Connection
- Above Ground Conduit
- 2/0
- 4"C
- Pump
- Sump
- Standard Electrical Connection
- Coolant Tubing
- 4 DLO 313 MCM
- per phase
- Sump Pump PN: SFDP2-012-035-21
- (near B6) 100AF, 20AT, 1P
- Two #12 CU
  One #12 CU GND
  In one 3/4" C.
- Pad Tub
- Primary
- WPT
- 14 AWG
- -----------------------
  -----------------------
  -----------------------
- (near B1) 1600AF, 1600AT, 3P, GFP
- (near B1) Four 400 Kcmil CU
  One #4/0 CU
  In one 3" C.
- Wave, CC: 18 AWG
- A, B: 10 AWG
- Smoke: 14 AWG
- Battery
- 1 Coolant line per conduit in 5" C
- Battery and output connections (secondary pad output busbars and connected cables) are supplied by Kenworth.
- 1 LV Control Line in 3/4" C
- 100AF, 20AT, 3P
- 1 Coolant line per conduit in 3"C
- Three #12 CU; One #12 CU GND; In one 3/4" C.
- 100AF, 10AT, 3P
- Current Reading
- Three #12 CU, One #12 CU GND
  In 3/4" C.
- Wire Color Definitions:
- Coolant Lines
- OV-
- OV+
- Temperature Reading
- Labels drawn without touching a wire or pin: 24V_DC_Cool, GND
